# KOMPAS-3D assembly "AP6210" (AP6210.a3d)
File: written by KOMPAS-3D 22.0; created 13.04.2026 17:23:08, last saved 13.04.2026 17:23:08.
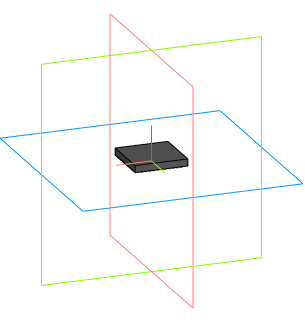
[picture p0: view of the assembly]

Document properties: Автор: Andrey; Полное имя файла: C:\Users\User1\Documents\AP6210.a3d

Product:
- Component [assembly]: ASSEMBLY  | qty 1  | source file: ASSEMBLY_16.a3d
- Part/product: AP6210
    Комментарий: AP6210

Referenced files in C:\Users\User1\Documents\: ASSEMBLY_16.a3d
